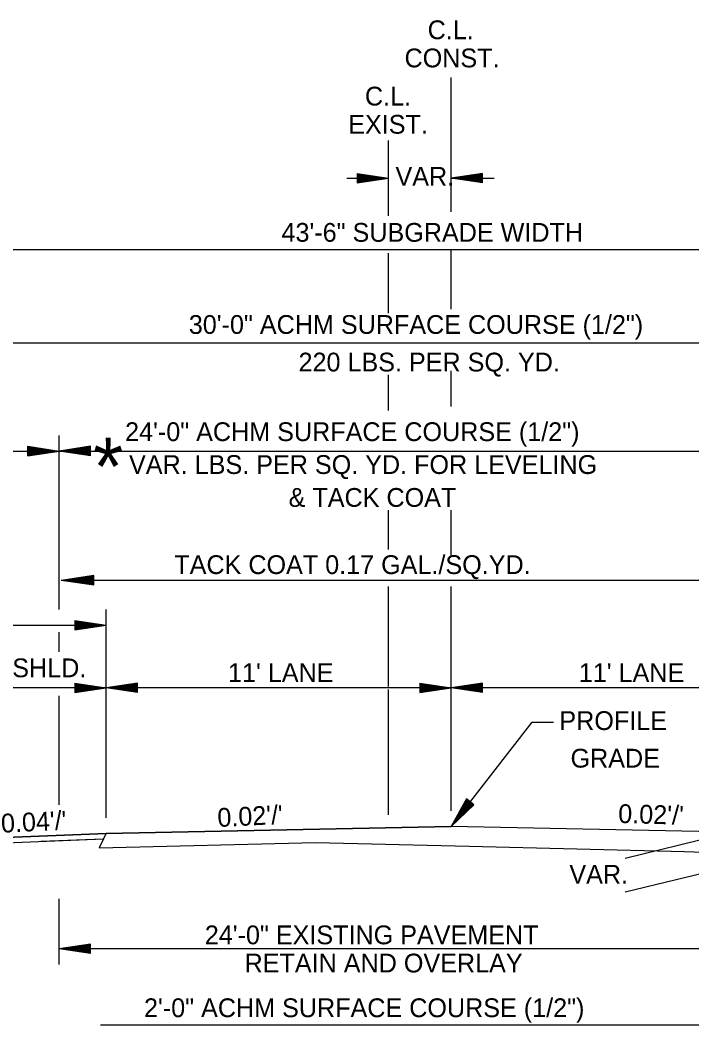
# Model space of a CAD drawing. Extents: x -900 to 15312, y 1857 to 2945.
# Drawn here: x -606.8 to -392.5, y 2163.6 to 2484.5 of the extents above; entities that cross this region are included whole.
import ezdxf

# ---------------------------------------------------------------- set-up
doc = ezdxf.new("R2010")
doc.units = 0
for name, color, linetype in [('Default', 7, 'Continuous'), ('R_Annotation', 7, 'Continuous'), ('R_Centerline', 7, 'Continuous'), ('R_Dimension', 7, 'Continuous')]:
    doc.layers.add(name, color=color, linetype=linetype)

msp = doc.modelspace()

# ---------------------------------------------------------------- linework, layer by layer
at = {"layer": 'Default'}
for p, q in [((-469.31, 2226.91), (-579.31, 2224.71)), ((-379.31, 2225.11), (-469.31, 2226.91)), ((-581.6, 2220.11), (-512.59, 2221.78))]:
    msp.add_line(p, q, dxfattribs=at)
for points in [[(-579.31, 2224.71), (-580.16, 2223), (-581.6, 2220.11)], [(-512.59, 2221.78), (-463.54, 2220.63), (-394.78, 2218.98), (-379.31, 2218.42)]]:
    msp.add_lwpolyline(points, dxfattribs=at)
at = {"layer": 'R_Annotation'}
for p, q in [((-619.31, 2223.11), (-579.31, 2224.71)), ((-579.31, 2224.71), (-469.31, 2226.91)), ((-359.31, 2224.71), (-469.31, 2226.91)), ((-600.16, 2222.2), (-580.16, 2223))]:
    msp.add_line(p, q, dxfattribs=at)
at = {"layer": 'R_Centerline'}
for p, q in [((-469.31, 2423.2), (-469.31, 2466.15)), ((-489.31, 2421.94), (-489.31, 2446.01)), ((-489.31, 2390.86), (-489.31, 2409.98)), ((-469.31, 2392.12), (-469.31, 2411.24)), ((-469.31, 2361.01), (-469.31, 2372.43)), ((-489.31, 2359.75), (-489.31, 2371.17)), ((-489.31, 2315.43), (-489.31, 2328)), ((-469.31, 2313.62), (-469.31, 2328)), ((-489.31, 2271.68), (-489.31, 2303.62)), ((-469.31, 2231.91), (-469.31, 2303.62)), ((-489.31, 2230.64), (-489.31, 2270.64))]:
    msp.add_line(p, q, dxfattribs=at)
at = {"layer": 'R_Dimension'}
for p, q in [((-502.57, 2433.97), (-489.31, 2433.97)), ((-499.31, 2435.47), (-489.31, 2433.97)), ((-499.31, 2435.47), (-499.31, 2432.47)), ((-499.31, 2435.22), (-490.98, 2433.97)), ((-499.31, 2434.97), (-492.7, 2433.97)), ((-499.31, 2434.72), (-494.37, 2433.97)), ((-499.31, 2434.46), (-496.06, 2433.97)), ((-499.31, 2434.21), (-497.73, 2433.97)), ((-499.31, 2432.47), (-489.31, 2433.97)), ((-499.31, 2433.48), (-496.06, 2433.97)), ((-499.31, 2432.98), (-492.7, 2433.97)), ((-499.31, 2432.72), (-490.98, 2433.97)), ((-499.31, 2433.23), (-494.37, 2433.97)), ((-499.31, 2433.74), (-497.73, 2433.97)), ((-459.31, 2435.47), (-469.31, 2433.97)), ((-459.31, 2432.47), (-469.31, 2433.97)), ((-469.31, 2433.97), (-455.53, 2433.97)), ((-459.31, 2435.22), (-467.64, 2433.97)), ((-459.31, 2432.72), (-467.64, 2433.97)), ((-459.31, 2434.97), (-465.92, 2433.97)), ((-459.31, 2432.98), (-465.92, 2433.97)), ((-459.31, 2434.72), (-464.25, 2433.97)), ((-459.31, 2433.23), (-464.25, 2433.97)), ((-459.31, 2434.46), (-462.56, 2433.97)), ((-459.31, 2433.49), (-462.56, 2433.97)), ((-459.31, 2434.21), (-460.89, 2433.97)), ((-459.31, 2433.74), (-460.89, 2433.97)), ((-459.31, 2432.47), (-459.31, 2435.47)), ((-687.73, 2411.24), (-250.88, 2411.24)), ((-319.31, 2381.24), (-619.31, 2381.24)), ((-594.31, 2296.24), (-594.31, 2351.84)), ((-741.93, 2346.84), (-300.92, 2346.84)), ((-604.31, 2348.34), (-594.31, 2346.84)), ((-604.31, 2345.34), (-604.31, 2348.34)), ((-604.31, 2348.09), (-595.98, 2346.84)), ((-604.31, 2347.83), (-597.7, 2346.84)), ((-604.31, 2347.58), (-599.36, 2346.84)), ((-604.31, 2347.33), (-601.06, 2346.84)), ((-604.31, 2347.07), (-602.73, 2346.84)), ((-604.31, 2345.34), (-594.31, 2346.84)), ((-604.31, 2346.35), (-601.06, 2346.84)), ((-604.31, 2345.84), (-597.7, 2346.84)), ((-604.31, 2345.59), (-595.98, 2346.84)), ((-604.31, 2346.09), (-599.36, 2346.84)), ((-604.31, 2346.6), (-602.73, 2346.84)), ((-584.31, 2348.34), (-594.31, 2346.84)), ((-584.31, 2345.34), (-594.31, 2346.84)), ((-584.31, 2348.09), (-592.64, 2346.84)), ((-584.31, 2345.59), (-592.64, 2346.84)), ((-584.31, 2347.83), (-590.92, 2346.84)), ((-584.31, 2345.84), (-590.92, 2346.84)), ((-584.31, 2347.58), (-589.25, 2346.84)), ((-584.31, 2346.09), (-589.25, 2346.84)), ((-584.31, 2347.33), (-587.56, 2346.84)), ((-584.31, 2346.35), (-587.56, 2346.84)), ((-584.31, 2347.07), (-585.89, 2346.84)), ((-584.31, 2346.6), (-585.89, 2346.84)), ((-584.31, 2345.34), (-584.31, 2348.34)), ((-583.26, 2307.09), (-593.67, 2305.53)), ((-583.26, 2303.97), (-593.67, 2305.53)), ((-379.27, 2305.53), (-593.67, 2305.53)), ((-583.26, 2306.83), (-591.93, 2305.53)), ((-583.26, 2304.23), (-591.93, 2305.53)), ((-583.26, 2306.56), (-590.14, 2305.53)), ((-583.26, 2304.5), (-590.14, 2305.53)), ((-583.26, 2306.3), (-588.41, 2305.53)), ((-583.26, 2304.76), (-588.41, 2305.53)), ((-583.26, 2306.04), (-586.64, 2305.53)), ((-583.26, 2305.03), (-586.64, 2305.53)), ((-583.26, 2305.77), (-584.9, 2305.53)), ((-583.26, 2305.29), (-584.9, 2305.53)), ((-583.26, 2303.97), (-583.26, 2307.09)), ((-553.66, 2305.53), (-554.92, 2305.53)), ((-579.31, 2271.24), (-579.31, 2296.24)), ((-779.31, 2291.24), (-579.31, 2291.24)), ((-589.31, 2292.74), (-579.31, 2291.24)), ((-589.31, 2292.74), (-589.31, 2289.74)), ((-589.31, 2292.49), (-580.98, 2291.24)), ((-589.31, 2292.23), (-582.7, 2291.24)), ((-589.31, 2291.98), (-584.36, 2291.24)), ((-589.31, 2291.72), (-586.06, 2291.24)), ((-589.31, 2291.47), (-587.73, 2291.24)), ((-589.31, 2289.74), (-579.31, 2291.24)), ((-589.31, 2290.75), (-586.06, 2291.24)), ((-589.31, 2290.24), (-582.7, 2291.24)), ((-589.31, 2289.99), (-580.98, 2291.24)), ((-589.31, 2290.49), (-584.36, 2291.24)), ((-589.31, 2291), (-587.73, 2291.24)), ((-594.31, 2282.7), (-594.31, 2289.04)), ((-589.31, 2272.74), (-579.31, 2271.24)), ((-589.31, 2272.74), (-589.31, 2269.74)), ((-589.31, 2272.49), (-580.98, 2271.24)), ((-589.31, 2272.23), (-582.7, 2271.24)), ((-589.31, 2271.98), (-584.36, 2271.24)), ((-569.31, 2272.74), (-579.31, 2271.24)), ((-569.31, 2272.49), (-577.64, 2271.24)), ((-569.31, 2272.23), (-575.92, 2271.24)), ((-569.31, 2271.98), (-574.25, 2271.24)), ((-569.31, 2269.74), (-569.31, 2272.74)), ((-479.31, 2272.74), (-469.31, 2271.24)), ((-479.31, 2272.74), (-479.31, 2269.74)), ((-479.31, 2272.49), (-470.98, 2271.24)), ((-479.31, 2272.23), (-472.7, 2271.24)), ((-479.31, 2271.98), (-474.36, 2271.24)), ((-459.31, 2272.74), (-469.31, 2271.24)), ((-459.31, 2272.49), (-467.64, 2271.24)), ((-459.31, 2272.23), (-465.92, 2271.24)), ((-459.31, 2271.98), (-464.25, 2271.24)), ((-459.31, 2269.74), (-459.31, 2272.74)), ((-250.88, 2271.24), (-687.73, 2271.24)), ((-589.31, 2271.72), (-586.06, 2271.24)), ((-589.31, 2271.47), (-587.73, 2271.24)), ((-589.31, 2269.74), (-579.31, 2271.24)), ((-589.31, 2270.75), (-586.06, 2271.24)), ((-589.31, 2270.24), (-582.7, 2271.24)), ((-589.31, 2269.99), (-580.98, 2271.24)), ((-589.31, 2270.49), (-584.36, 2271.24)), ((-589.31, 2271), (-587.73, 2271.24)), ((-579.31, 2229.71), (-579.31, 2271.24)), ((-569.31, 2269.74), (-579.31, 2271.24)), ((-569.31, 2269.99), (-577.64, 2271.24)), ((-569.31, 2270.24), (-575.92, 2271.24)), ((-569.31, 2270.49), (-574.25, 2271.24)), ((-569.31, 2271.73), (-572.56, 2271.24)), ((-569.31, 2270.75), (-572.56, 2271.24)), ((-569.31, 2271.47), (-570.89, 2271.24)), ((-569.31, 2271), (-570.89, 2271.24)), ((-479.31, 2271.72), (-476.06, 2271.24)), ((-479.31, 2271.47), (-477.73, 2271.24)), ((-479.31, 2269.74), (-469.31, 2271.24)), ((-479.31, 2270.75), (-476.06, 2271.24)), ((-479.31, 2270.24), (-472.7, 2271.24)), ((-479.31, 2269.99), (-470.98, 2271.24)), ((-479.31, 2270.49), (-474.36, 2271.24)), ((-479.31, 2271), (-477.73, 2271.24)), ((-459.31, 2269.74), (-469.31, 2271.24)), ((-459.31, 2269.99), (-467.64, 2271.24)), ((-459.31, 2270.24), (-465.92, 2271.24)), ((-459.31, 2270.49), (-464.25, 2271.24)), ((-459.31, 2271.73), (-462.56, 2271.24)), ((-459.31, 2270.75), (-462.56, 2271.24)), ((-459.31, 2271.47), (-460.89, 2271.24)), ((-459.31, 2271), (-460.89, 2271.24)), ((-594.31, 2233.81), (-594.31, 2268.61)), ((-464.36, 2235.73), (-469.31, 2226.91)), ((-461.99, 2233.89), (-469.31, 2226.91)), ((-464.16, 2235.57), (-468.28, 2228.22)), ((-462.19, 2234.04), (-468.28, 2228.22)), ((-463.96, 2235.42), (-467.23, 2229.58)), ((-462.39, 2234.2), (-467.23, 2229.58)), ((-463.77, 2235.26), (-466.21, 2230.9)), ((-462.59, 2234.35), (-466.21, 2230.9)), ((-463.56, 2235.11), (-465.17, 2232.24)), ((-462.79, 2234.51), (-465.17, 2232.24)), ((-461.99, 2233.89), (-464.36, 2235.73)), ((-463.36, 2234.95), (-464.15, 2233.56)), ((-462.99, 2234.66), (-464.15, 2233.56)), ((-579.31, 2224.71), (-619.31, 2223.11)), ((-580.16, 2223), (-579.31, 2224.71)), ((-379.31, 2225.11), (-413.76, 2216.75)), ((-620.16, 2221.4), (-580.16, 2223)), ((-379.31, 2214.27), (-413.76, 2205.91)), ((-594.31, 2182.88), (-594.31, 2203.85)), ((-584.31, 2189.38), (-594.31, 2187.88)), ((-584.31, 2189.13), (-592.64, 2187.88)), ((-584.31, 2188.87), (-590.92, 2187.88)), ((-584.31, 2188.62), (-589.25, 2187.88)), ((-584.31, 2186.38), (-584.31, 2189.38)), ((-584.31, 2186.38), (-594.31, 2187.88)), ((-379.31, 2187.88), (-594.31, 2187.88)), ((-584.31, 2186.63), (-592.64, 2187.88)), ((-584.31, 2186.88), (-590.92, 2187.88)), ((-584.31, 2187.13), (-589.25, 2187.88)), ((-584.31, 2188.37), (-587.56, 2187.88)), ((-584.31, 2187.39), (-587.56, 2187.88)), ((-584.31, 2188.11), (-585.89, 2187.88)), ((-584.31, 2187.64), (-585.89, 2187.88)), ((-581.18, 2163.57), (-379.41, 2163.57))]:
    msp.add_line(p, q, dxfattribs=at)
msp.add_lwpolyline([(-469.31, 2226.91), (-443.46, 2260.23), (-436.59, 2260.23)], dxfattribs=at)

# ---------------------------------------------------------------- texts
at = {"layer": 'R_Annotation'}
for s, height, p in [('C.L.', 6, (-476.77, 2478.36)), ('CONST.', 6, (-484.14, 2469.36)), ('C.L.', 6, (-496.77, 2457.17)), ('EXIST.', 6, (-502.11, 2448.17)), ('VAR.', 6, (-487.03, 2431.55)), ('43\'-6" SUBGRADE WIDTH', 6, (-523.4, 2413.66)), ('30\'-0" ACHM SURFACE COURSE (1/2")', 6, (-552.98, 2384.24)), ('220 LBS. PER SQ. YD.', 6, (-517.97, 2372.24)), ('24\'-0" ACHM SURFACE COURSE (1/2")', 6, (-573.3, 2350.01)), ('*', 18.39, (-583.49, 2332.71)), ('VAR. LBS. PER SQ. YD. FOR LEVELING', 6, (-572.05, 2339.51)), ('& TACK COAT', 6, (-521.12, 2329.01)), ('TACK COAT 0.17 GAL./SQ.YD.', 6, (-557.6, 2307.55)), ("4' SHLD.", 6, (-617.54, 2274.59)), ("11' LANE", 6, (-540.45, 2273.08)), ("11' LANE", 6, (-428.53, 2273.08)), ('PROFILE', 6, (-434.73, 2257.74)), ('GRADE', 6, (-431.18, 2245.74)), ('VAR.', 6, (-431.54, 2208.66)), ('24\'-0" EXISTING PAVEMENT', 6, (-547.87, 2189.32)), ('RETAIN AND OVERLAY', 6, (-535.18, 2180.32)), ('2\'-0" ACHM SURFACE COURSE (1/2")', 6, (-567.27, 2166.04))]:
    msp.add_text(s, height=height, dxfattribs=at).set_placement(p)
for s, rotation, p in [("0.02'/'", 2.7804, (-543.71, 2226.76)), ("0.02'/'", 358.3978, (-416.02, 2228.08)), ("0.04'/'", 2.7804, (-612.76, 2224.93))]:
    msp.add_text(s, height=6, rotation=rotation, dxfattribs=at).set_placement(p)

doc.saveas('drawing.dxf')
